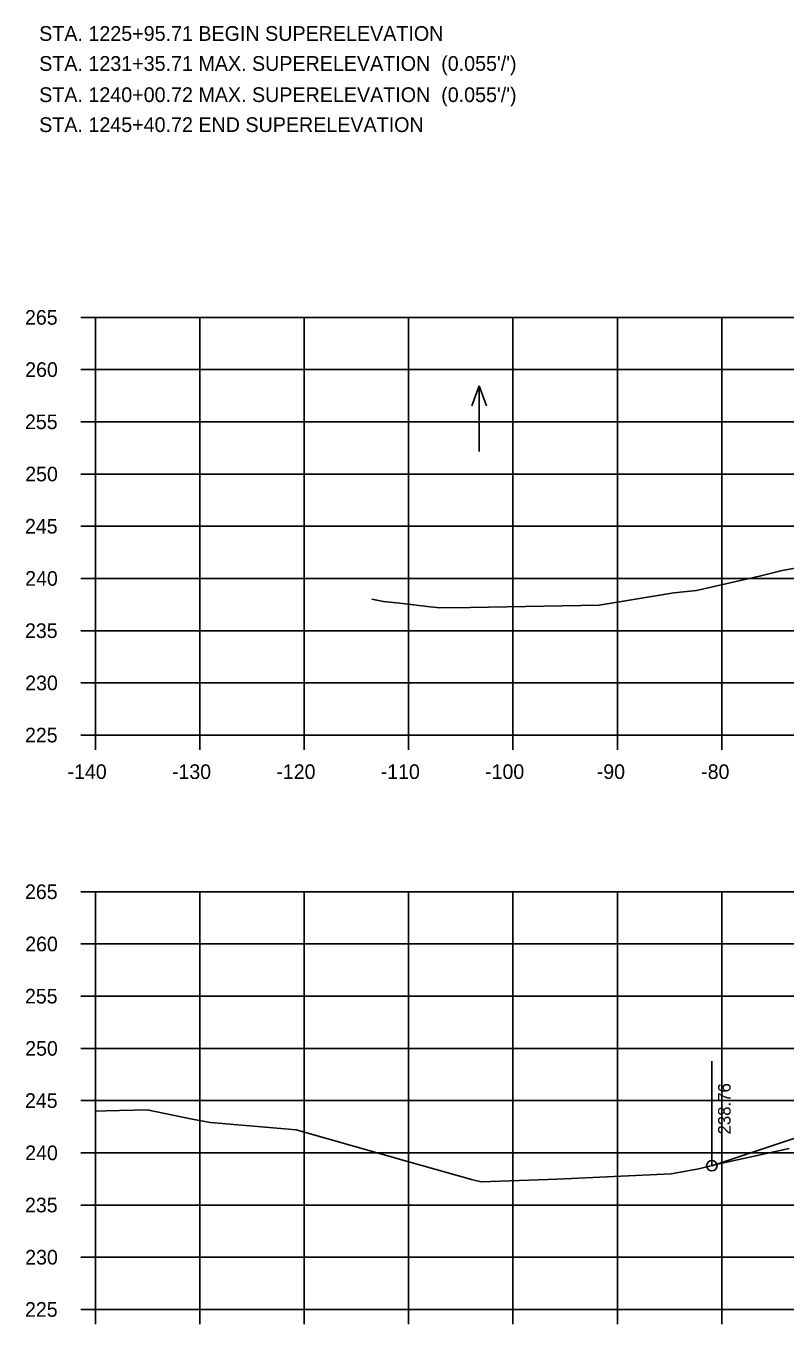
# Model space of a CAD drawing. Extents: x 1342547 to 1344156, y -1532351 to -1517216.
# Drawn here: x 1342556.2 to 1342628.9, y -1529290.8 to -1529166.5 of the extents above; entities that cross this region are included whole.
import ezdxf

# ---------------------------------------------------------------- set-up
doc = ezdxf.new("R2010")
doc.units = 0
for name, color, linetype in [('R_Axis', 7, 'Continuous'), ('R_Axis Annot', 7, 'Continuous'), ('R_Border Notes', 7, 'Continuous'), ('R_Exist Surface', 7, 'Continuous'), ('R_Fin Surface', 7, 'Continuous'), ('R_Grid', 7, 'Continuous'), ('R_No Plot', 7, 'Continuous'), ('R_Water', 7, 'Continuous'), ('R_Xsect Elev', 7, 'Continuous')]:
    doc.layers.add(name, color=color, linetype=linetype)

msp = doc.modelspace()

# ---------------------------------------------------------------- linework, layer by layer
at = {"layer": 'R_Axis'}
for p, q in [((1342561.47, -1529194.42), (1342562.87, -1529194.42)), ((1342562.87, -1529234.42), (1342562.87, -1529194.42)), ((1342561.47, -1529199.42), (1342562.87, -1529199.42)), ((1342561.47, -1529204.42), (1342562.87, -1529204.42)), ((1342561.47, -1529209.42), (1342562.87, -1529209.42)), ((1342561.47, -1529214.42), (1342562.87, -1529214.42)), ((1342561.47, -1529219.42), (1342562.87, -1529219.42)), ((1342561.47, -1529224.42), (1342562.87, -1529224.42)), ((1342561.47, -1529229.42), (1342562.87, -1529229.42)), ((1342561.47, -1529234.42), (1342562.87, -1529234.42)), ((1342562.87, -1529234.42), (1342842.87, -1529234.42)), ((1342562.87, -1529235.82), (1342562.87, -1529234.42)), ((1342572.87, -1529235.82), (1342572.87, -1529234.42)), ((1342582.87, -1529235.82), (1342582.87, -1529234.42)), ((1342592.87, -1529235.82), (1342592.87, -1529234.42)), ((1342602.87, -1529235.82), (1342602.87, -1529234.42)), ((1342612.87, -1529235.82), (1342612.87, -1529234.42)), ((1342622.87, -1529235.82), (1342622.87, -1529234.42)), ((1342561.47, -1529249.42), (1342562.87, -1529249.42)), ((1342562.87, -1529289.42), (1342562.87, -1529249.42)), ((1342561.47, -1529254.42), (1342562.87, -1529254.42)), ((1342561.47, -1529259.42), (1342562.87, -1529259.42)), ((1342561.47, -1529264.42), (1342562.87, -1529264.42)), ((1342561.47, -1529269.42), (1342562.87, -1529269.42)), ((1342561.47, -1529274.42), (1342562.87, -1529274.42)), ((1342561.47, -1529279.42), (1342562.87, -1529279.42)), ((1342561.47, -1529284.42), (1342562.87, -1529284.42)), ((1342561.47, -1529289.42), (1342562.87, -1529289.42)), ((1342562.87, -1529289.42), (1342842.87, -1529289.42)), ((1342562.87, -1529290.82), (1342562.87, -1529289.42)), ((1342572.87, -1529290.82), (1342572.87, -1529289.42)), ((1342582.87, -1529290.82), (1342582.87, -1529289.42)), ((1342592.87, -1529290.82), (1342592.87, -1529289.42)), ((1342602.87, -1529290.82), (1342602.87, -1529289.42)), ((1342612.87, -1529290.82), (1342612.87, -1529289.42)), ((1342622.87, -1529290.82), (1342622.87, -1529289.42))]:
    msp.add_line(p, q, dxfattribs=at)
at = {"layer": 'R_Exist Surface'}
for points in [[(1342589.34, -1529221.4), (1342590.45, -1529221.64), (1342592.03, -1529221.8), (1342594.65, -1529222.09), (1342595.82, -1529222.24), (1342598.76, -1529222.2), (1342611.14, -1529221.98), (1342618.27, -1529220.81), (1342620.44, -1529220.58), (1342626.62, -1529219.18), (1342628.65, -1529218.66), (1342640.41, -1529216.55)], [(1342562.87, -1529270.42), (1342563.87, -1529270.4), (1342567.81, -1529270.32), (1342572.14, -1529271.19), (1342573.88, -1529271.53), (1342580.62, -1529272.1), (1342580.63, -1529272.1), (1342580.63, -1529272.1), (1342580.63, -1529272.1), (1342582.1, -1529272.21), (1342592.9, -1529275.29), (1342598.91, -1529276.99), (1342599.81, -1529277.2), (1342607.09, -1529276.96), (1342618.01, -1529276.44), (1342620.67, -1529275.97), (1342622.63, -1529275.48), (1342629.33, -1529274)]]:
    msp.add_lwpolyline(points, dxfattribs=at)
at = {"layer": 'R_Fin Surface'}
msp.add_lwpolyline([(1342621.92, -1529275.66), (1342643.37, -1529268.51), (1342650.4, -1529267.34), (1342662.34, -1529265.35), (1342671.37, -1529264.85), (1342673.37, -1529264.74), (1342702.87, -1529263.12), (1342732.37, -1529261.49), (1342734.37, -1529261.38), (1342745.87, -1529260.75), (1342754.07, -1529262.12), (1342790.46, -1529274.25)], dxfattribs=at)
at = {"layer": 'R_Grid'}
for p, q in [((1342562.87, -1529194.42), (1342842.87, -1529194.42)), ((1342562.87, -1529234.42), (1342562.87, -1529194.42)), ((1342572.87, -1529234.42), (1342572.87, -1529194.42)), ((1342582.87, -1529234.42), (1342582.87, -1529194.42)), ((1342592.87, -1529234.42), (1342592.87, -1529194.42)), ((1342602.87, -1529234.42), (1342602.87, -1529194.42)), ((1342612.87, -1529234.42), (1342612.87, -1529194.42)), ((1342622.87, -1529234.42), (1342622.87, -1529194.42)), ((1342562.87, -1529199.42), (1342842.87, -1529199.42)), ((1342562.87, -1529204.42), (1342842.87, -1529204.42)), ((1342562.87, -1529209.42), (1342842.87, -1529209.42)), ((1342562.87, -1529214.42), (1342842.87, -1529214.42)), ((1342562.87, -1529219.42), (1342842.87, -1529219.42)), ((1342562.87, -1529224.42), (1342842.87, -1529224.42)), ((1342562.87, -1529229.42), (1342842.87, -1529229.42)), ((1342562.87, -1529234.42), (1342842.87, -1529234.42)), ((1342562.87, -1529249.42), (1342842.87, -1529249.42)), ((1342562.87, -1529289.42), (1342562.87, -1529249.42)), ((1342572.87, -1529289.42), (1342572.87, -1529249.42)), ((1342582.87, -1529289.42), (1342582.87, -1529249.42)), ((1342592.87, -1529289.42), (1342592.87, -1529249.42)), ((1342602.87, -1529289.42), (1342602.87, -1529249.42)), ((1342612.87, -1529289.42), (1342612.87, -1529249.42)), ((1342622.87, -1529289.42), (1342622.87, -1529249.42)), ((1342562.87, -1529254.42), (1342842.87, -1529254.42)), ((1342562.87, -1529259.42), (1342842.87, -1529259.42)), ((1342562.87, -1529264.42), (1342842.87, -1529264.42)), ((1342562.87, -1529269.42), (1342842.87, -1529269.42)), ((1342562.87, -1529274.42), (1342842.87, -1529274.42)), ((1342562.87, -1529279.42), (1342842.87, -1529279.42)), ((1342562.87, -1529284.42), (1342842.87, -1529284.42)), ((1342562.87, -1529289.42), (1342842.87, -1529289.42))]:
    msp.add_line(p, q, dxfattribs=at)
at = {"layer": 'R_No Plot'}
msp.add_circle((1342621.92, -1529275.66), 0.5, dxfattribs=at)
at = {"layer": 'R_Water'}
for p, q in [((1342599.62, -1529200.97), (1342598.92, -1529202.89)), ((1342599.62, -1529207.26), (1342599.62, -1529200.97)), ((1342599.62, -1529200.97), (1342600.32, -1529202.89))]:
    msp.add_line(p, q, dxfattribs=at)
at = {"layer": 'R_Xsect Elev'}
msp.add_line((1342621.92, -1529275.66), (1342621.92, -1529265.66), dxfattribs=at)

# ---------------------------------------------------------------- texts
at = {"layer": 'R_Axis Annot'}
for s, p in [('265', (1342556.12, -1529195.12)), ('260', (1342556.14, -1529200.12)), ('255', (1342556.12, -1529205.12)), ('250', (1342556.14, -1529210.12)), ('245', (1342556.12, -1529215.12)), ('240', (1342556.14, -1529220.12)), ('235', (1342556.12, -1529225.12)), ('230', (1342556.14, -1529230.12)), ('225', (1342556.12, -1529235.12)), ('-140', (1342560.2, -1529238.62)), ('-130', (1342570.2, -1529238.62)), ('-120', (1342580.2, -1529238.62)), ('-110', (1342590.2, -1529238.62)), ('-100', (1342600.2, -1529238.62)), ('-90', (1342610.9, -1529238.62)), ('-80', (1342620.9, -1529238.62)), ('265', (1342556.12, -1529250.12)), ('260', (1342556.14, -1529255.12)), ('255', (1342556.12, -1529260.12)), ('250', (1342556.14, -1529265.12)), ('245', (1342556.12, -1529270.12)), ('240', (1342556.14, -1529275.12)), ('235', (1342556.12, -1529280.12)), ('230', (1342556.14, -1529285.12)), ('225', (1342556.12, -1529290.12))]:
    msp.add_text(s, height=1.4, dxfattribs=at).set_placement(p)
at = {"layer": 'R_Border Notes'}
for s, p in [('STA. 1225+95.71 BEGIN SUPERELEVATION', (1342557.48, -1529167.94)), ("STA. 1231+35.71 MAX. SUPERELEVATION  (0.055'/')", (1342557.48, -1529170.81)), ("STA. 1240+00.72 MAX. SUPERELEVATION  (0.055'/')", (1342557.48, -1529173.8)), ('STA. 1245+40.72 END SUPERELEVATION', (1342557.48, -1529176.67))]:
    msp.add_text(s, height=1.41, dxfattribs=at).set_placement(p)
at = {"layer": 'R_Xsect Elev'}
msp.add_text('238.76', height=1.2, rotation=90, dxfattribs=at).set_placement((1342623.72, -1529272.66))

doc.saveas('drawing.dxf')
